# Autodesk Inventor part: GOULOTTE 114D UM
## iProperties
Shininess: 21.0
Length Units: 11269
Angle Units: 11279
Time Units: 11290
Mass Units: 11283
Length Display Precision: 3
Angle Display Precision: 2
Created: 2001-03
Part Number: GOULOTTE 114D UM
Material: Par défaut
Document SubType Name: Modélisation
Designer: jost
Density: 0.0
Volumn: 0.0
Area: 0.0
PropertySet Name: Model Information
Control State: 0
Master: False
Checked Out: False
Author: jost
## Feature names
1. Extrusion1
